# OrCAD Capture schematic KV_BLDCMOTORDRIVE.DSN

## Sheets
1 TITLE PAGE: title: FRDM-MC-LVBLDC; rev: X1; company: Freescale Semiconductor; note: SCH-XXXXX PDF: SPF-XXXXX; note: 6501 William Cannon Drive West; note: Austin, TX 78735-8598
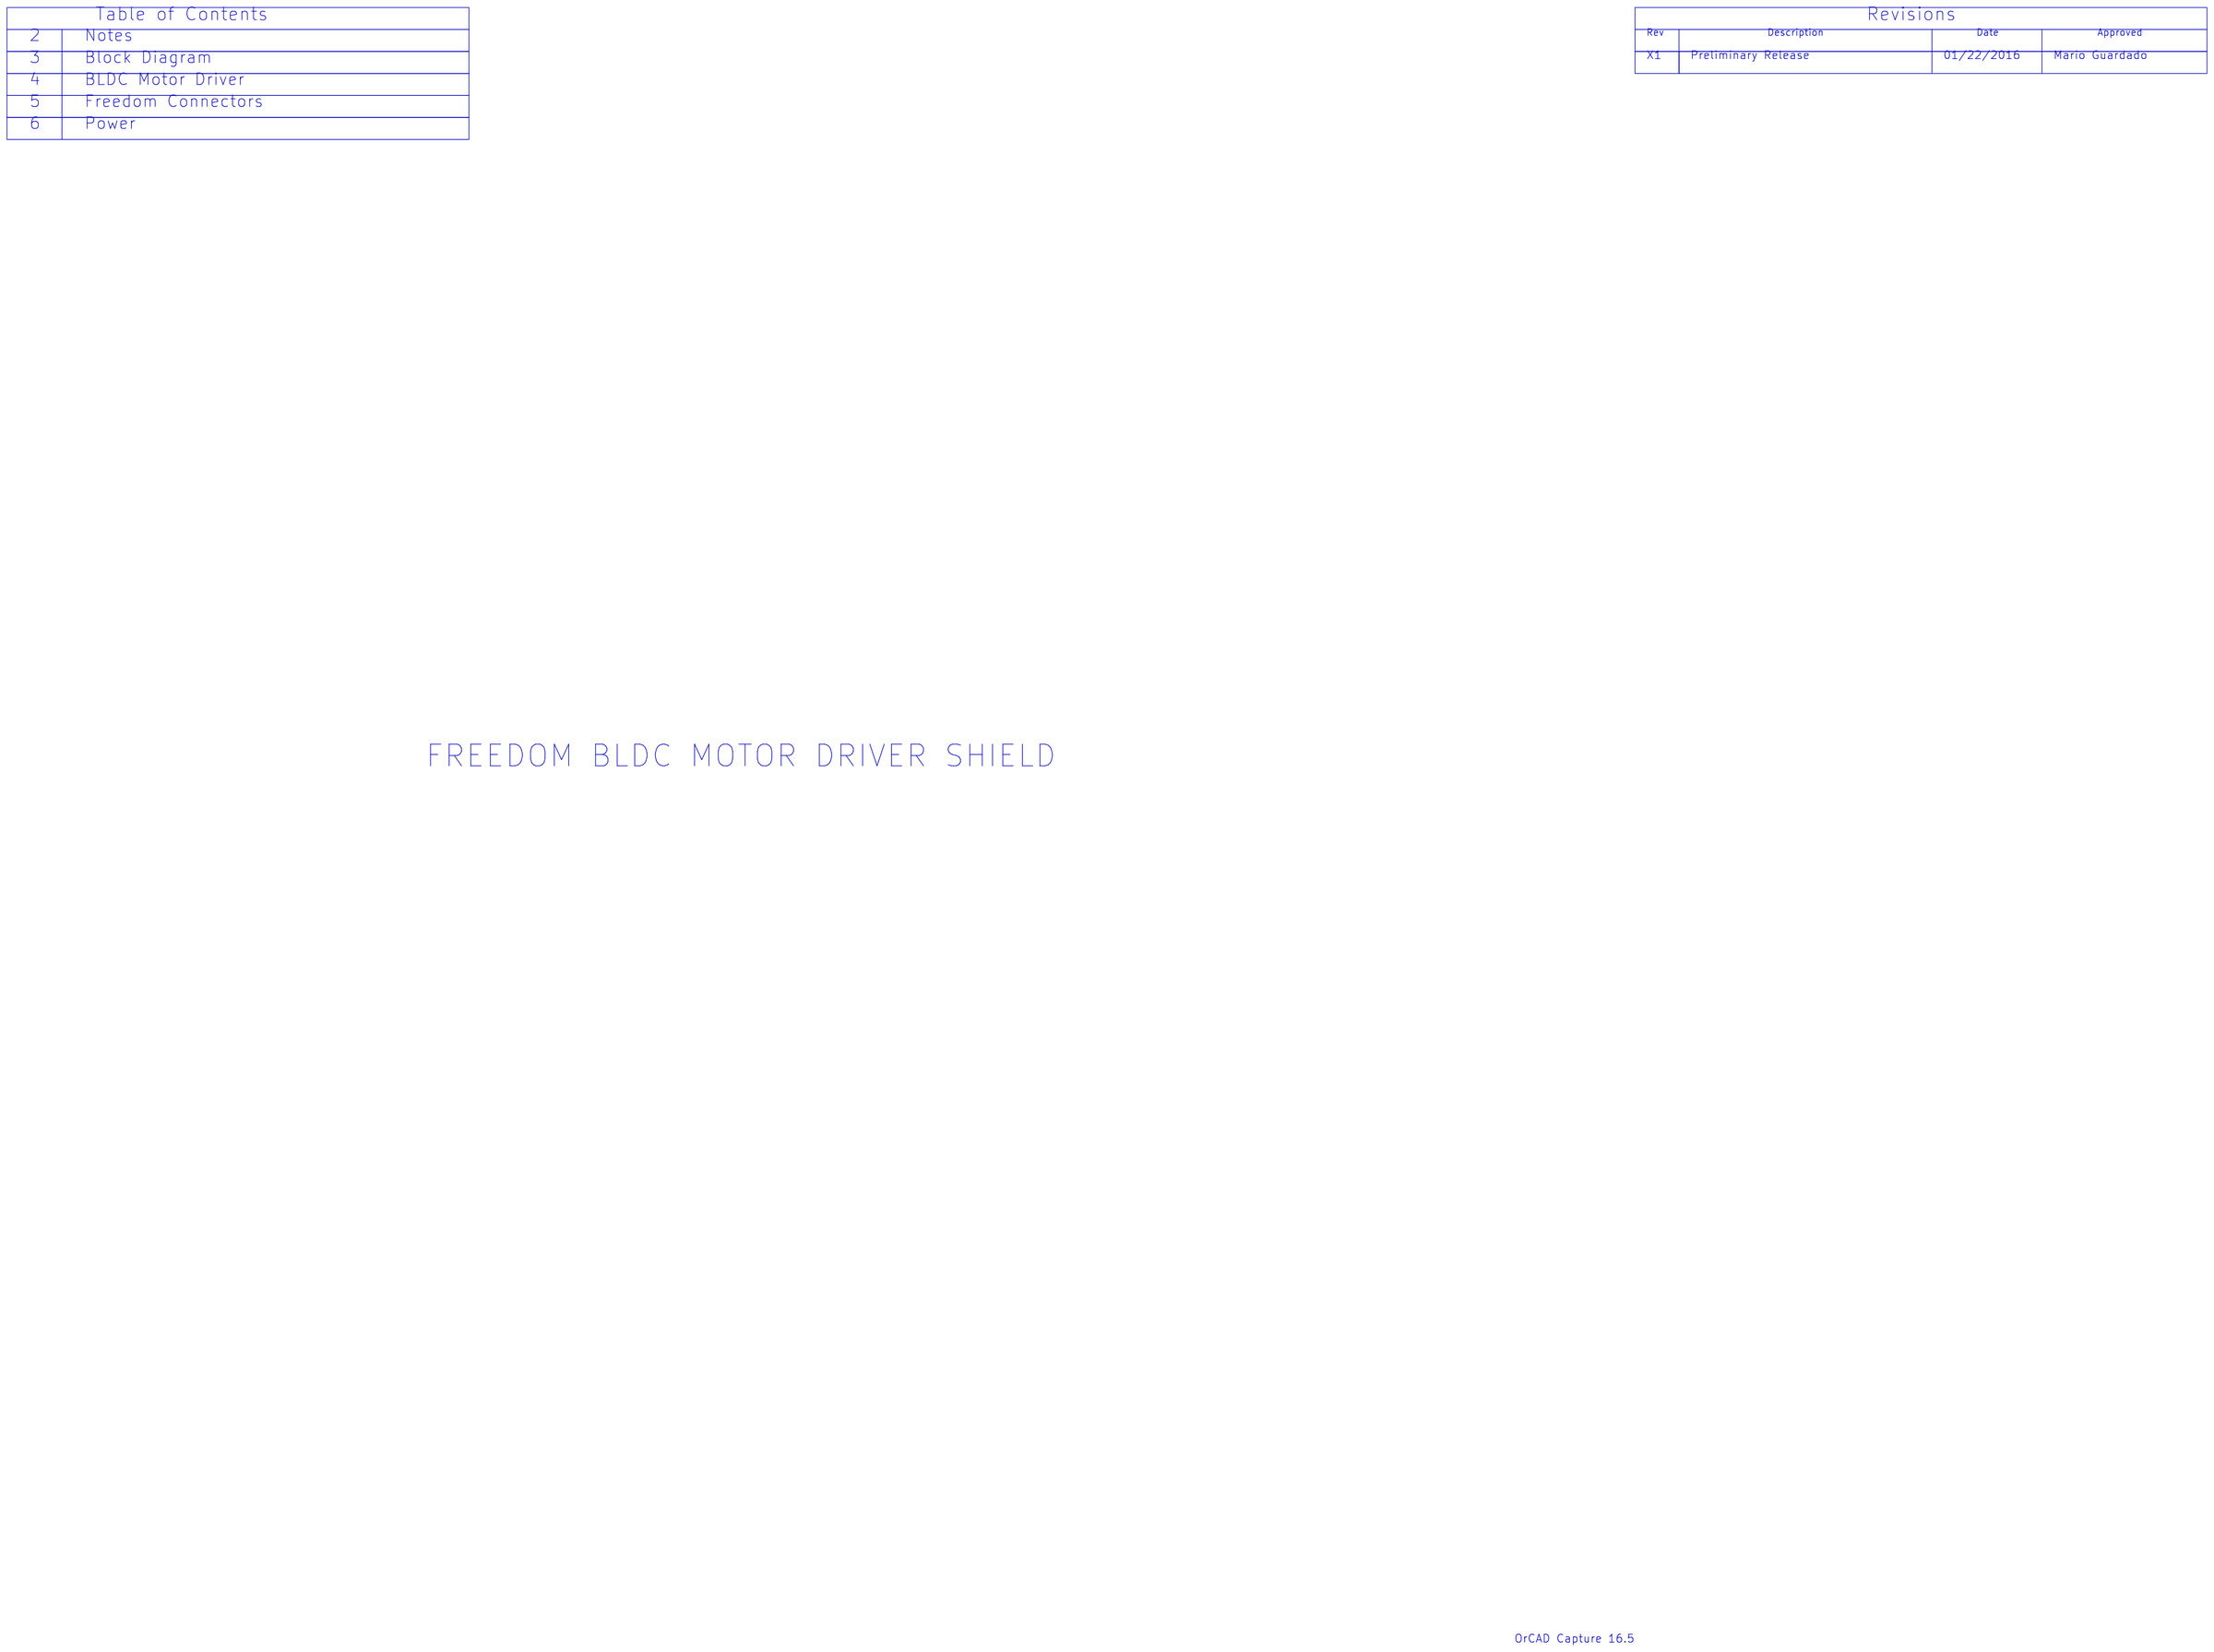
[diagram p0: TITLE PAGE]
2 NOTES
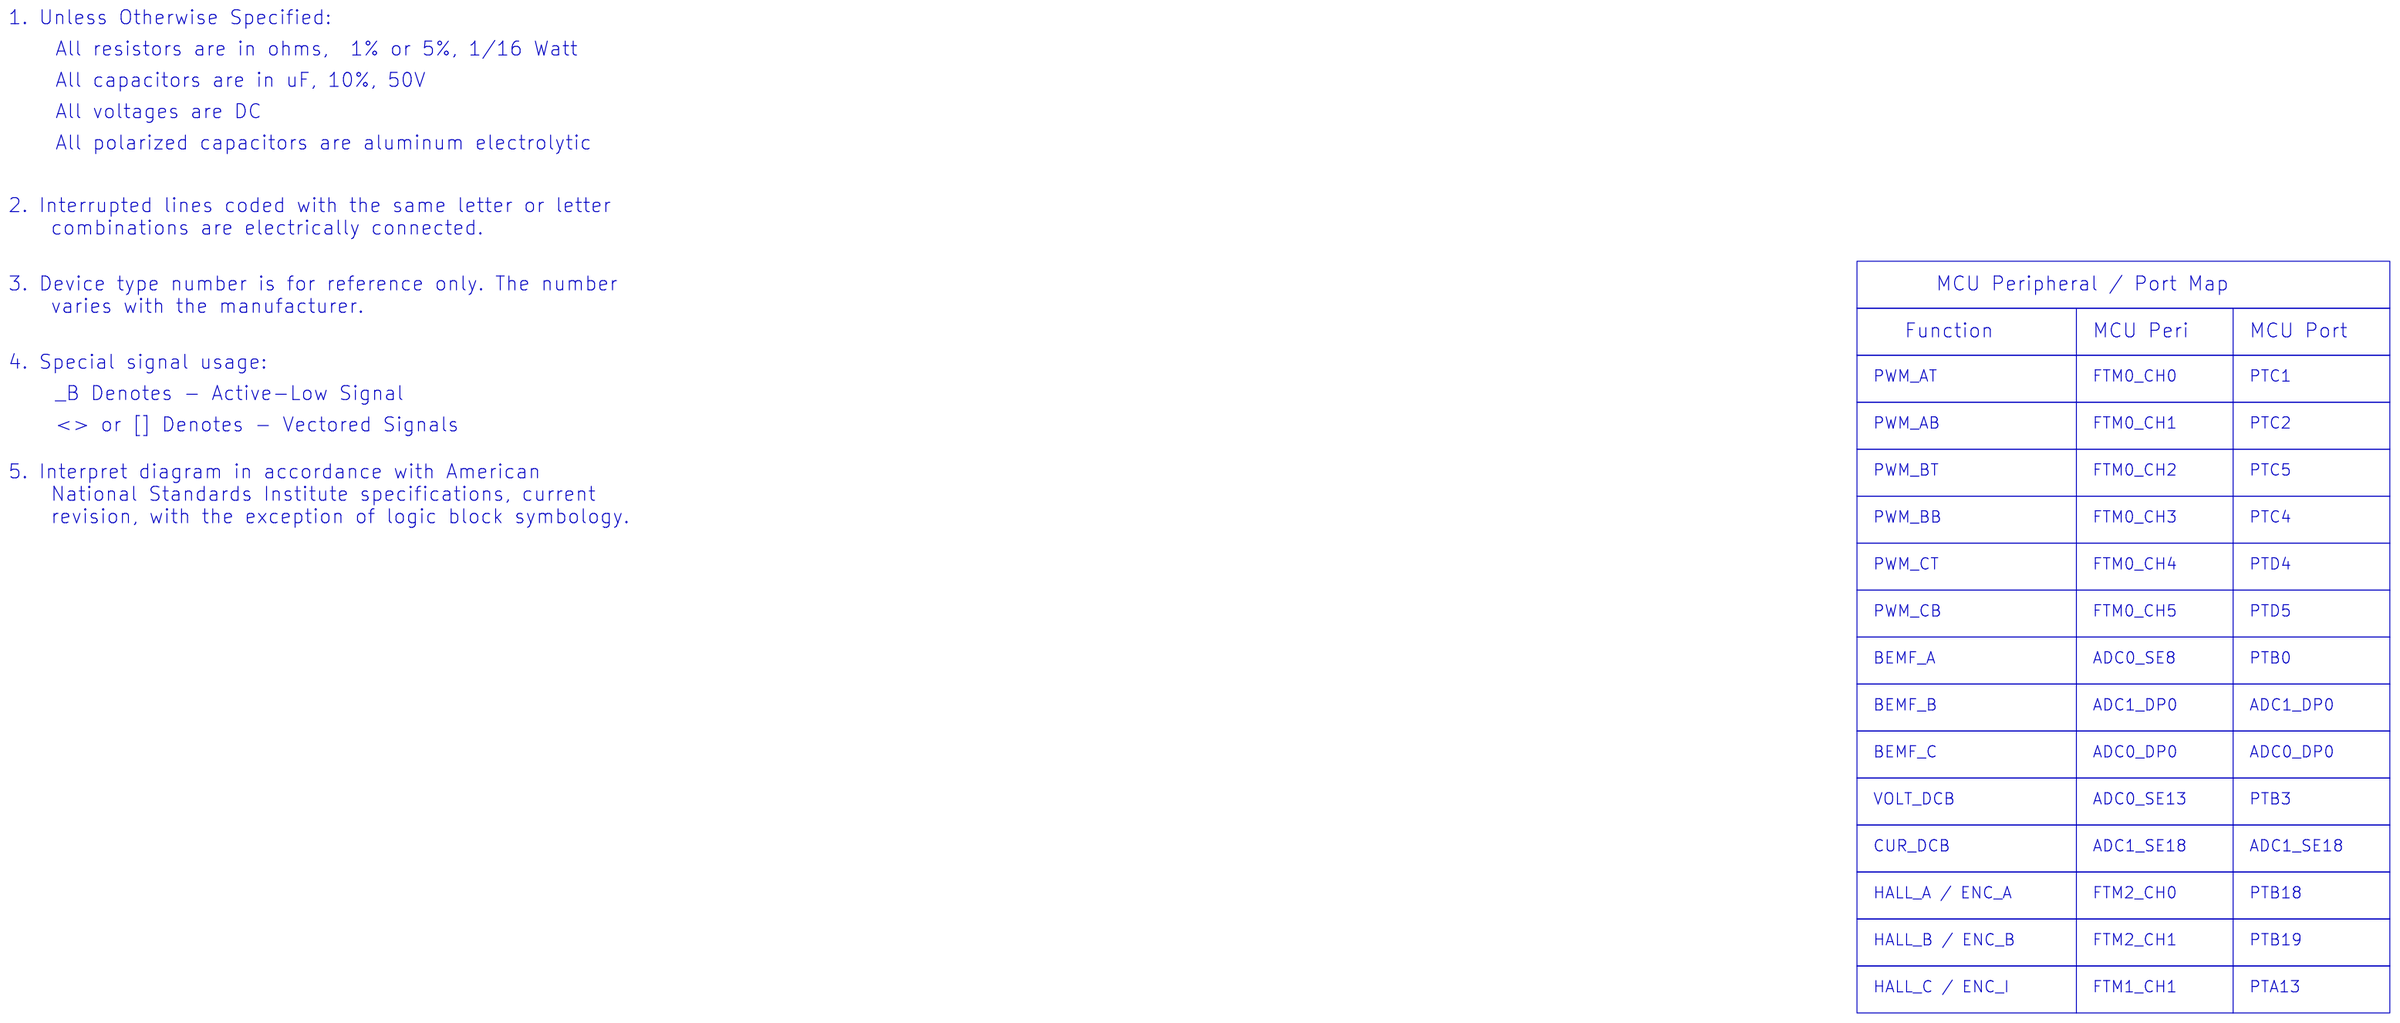
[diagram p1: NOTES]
3 BLOCK DIAGRAM
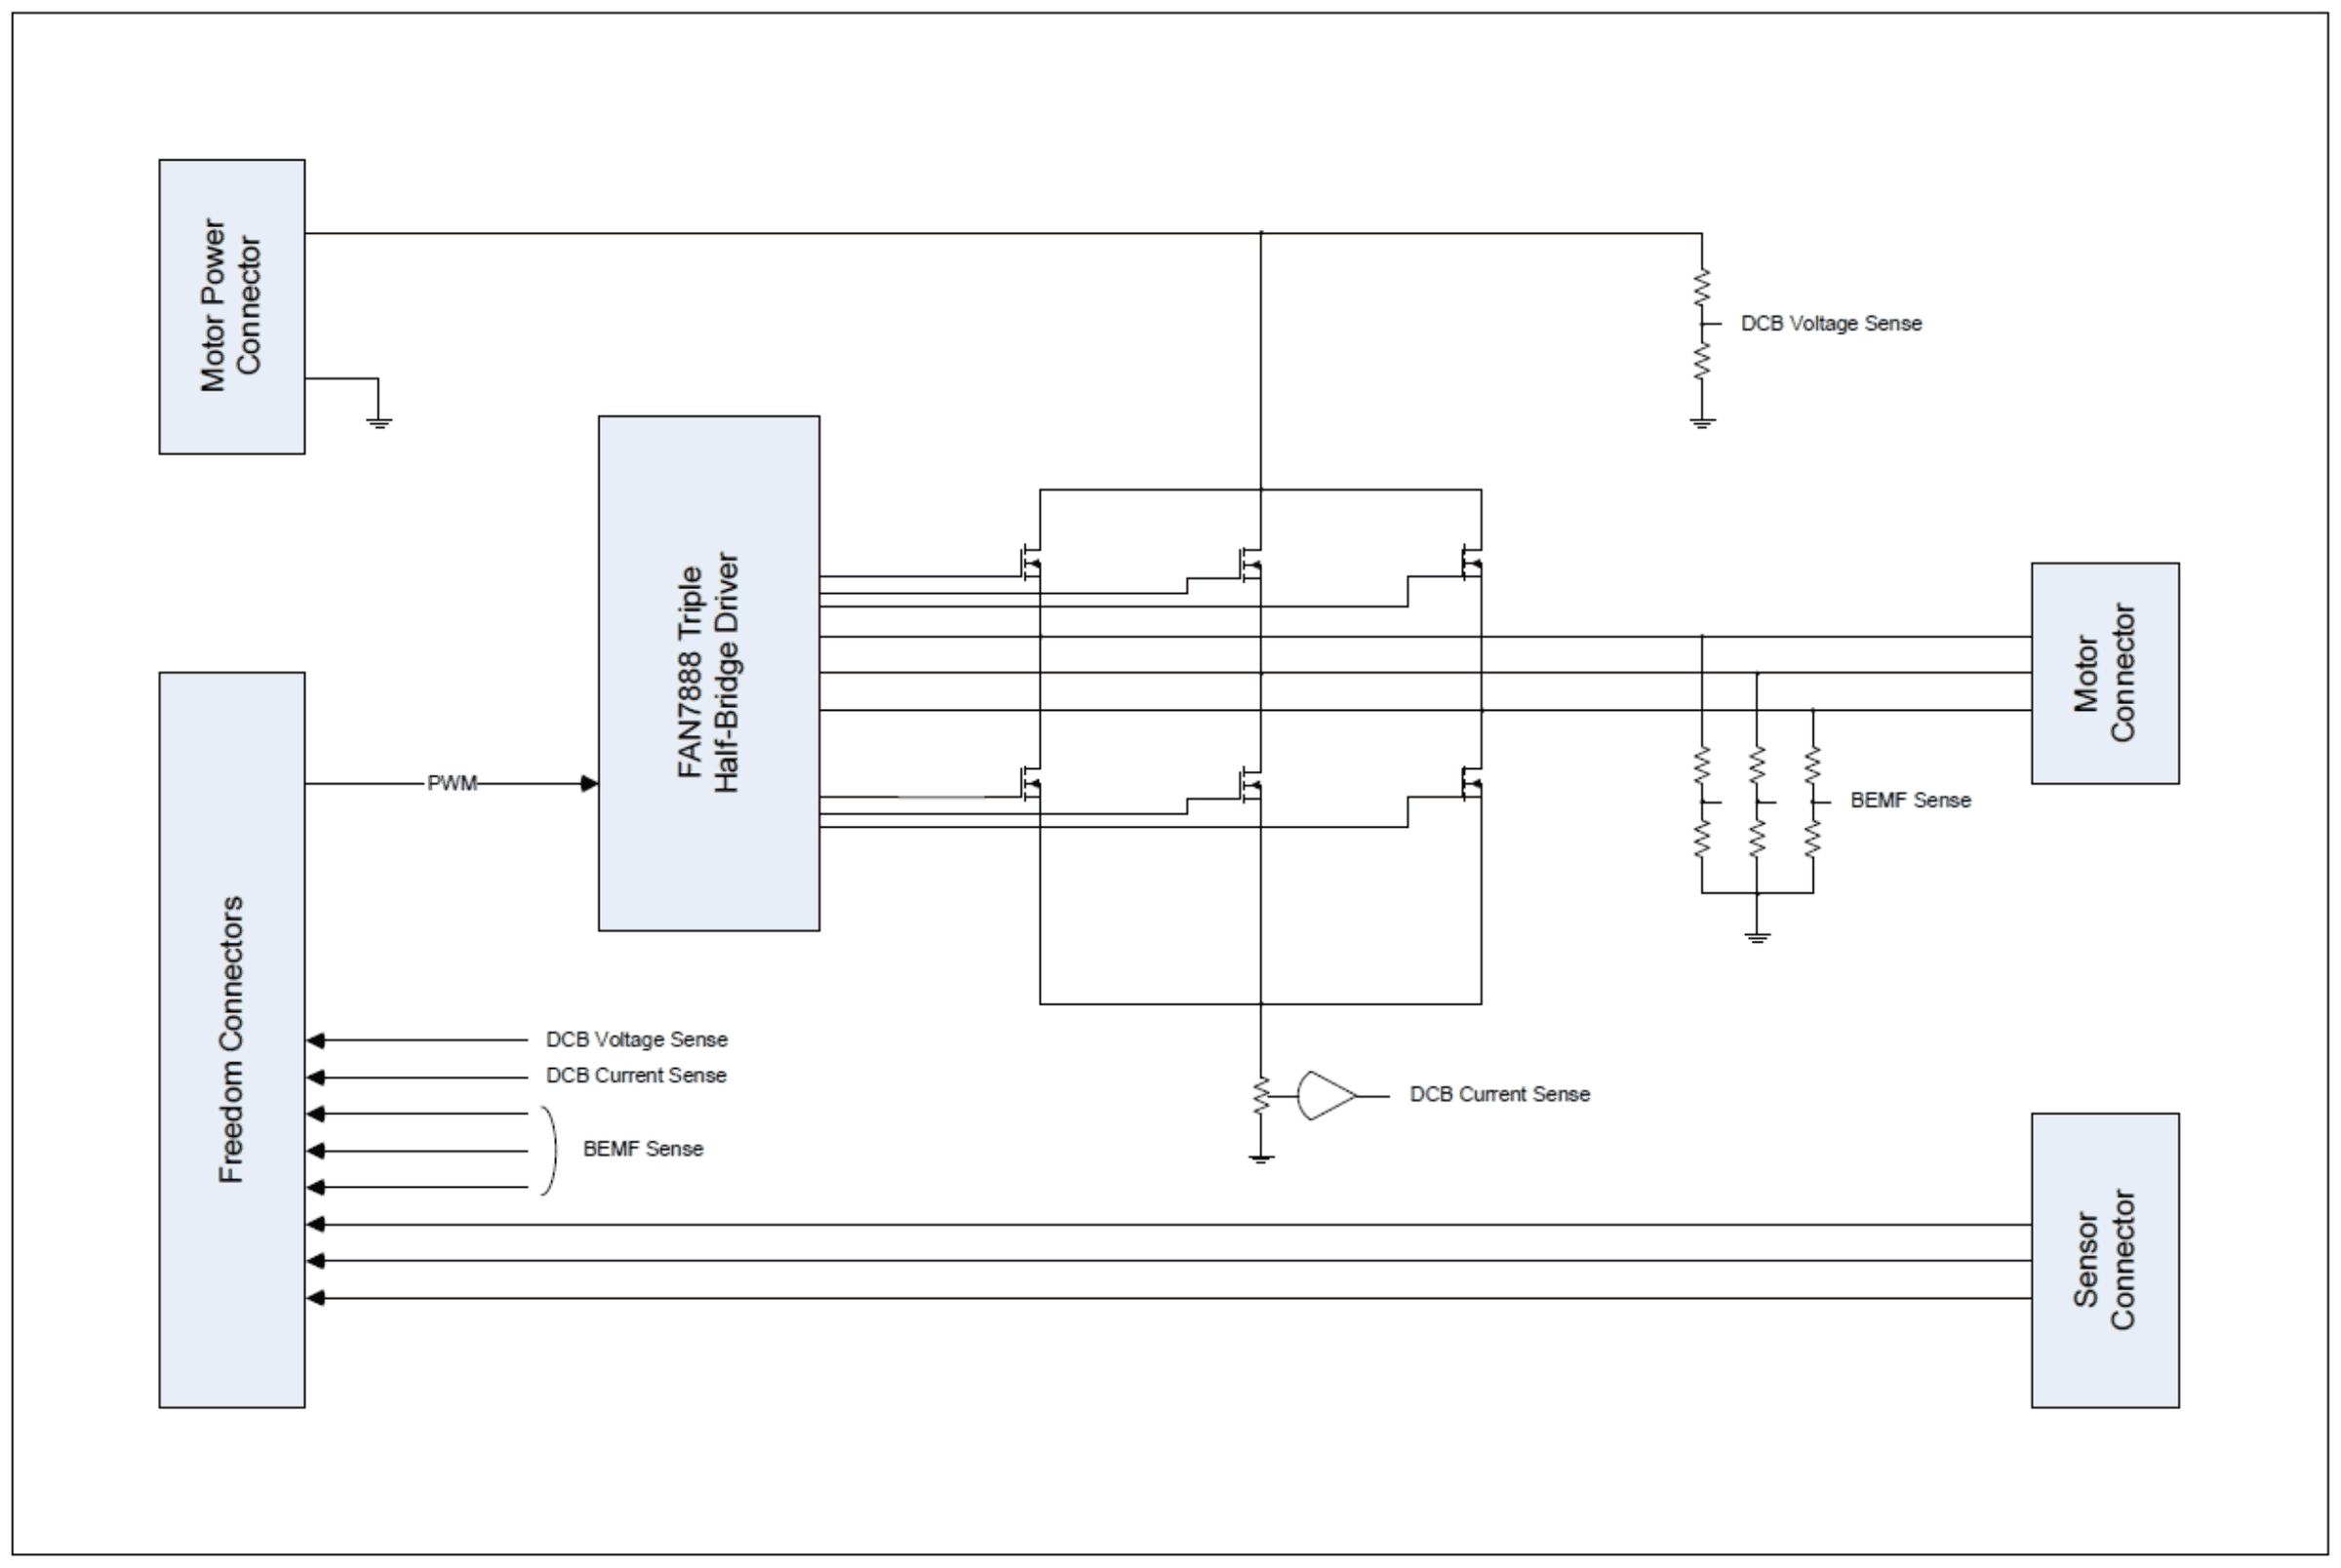
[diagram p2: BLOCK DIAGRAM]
4 MOTOR DRIVE: size C
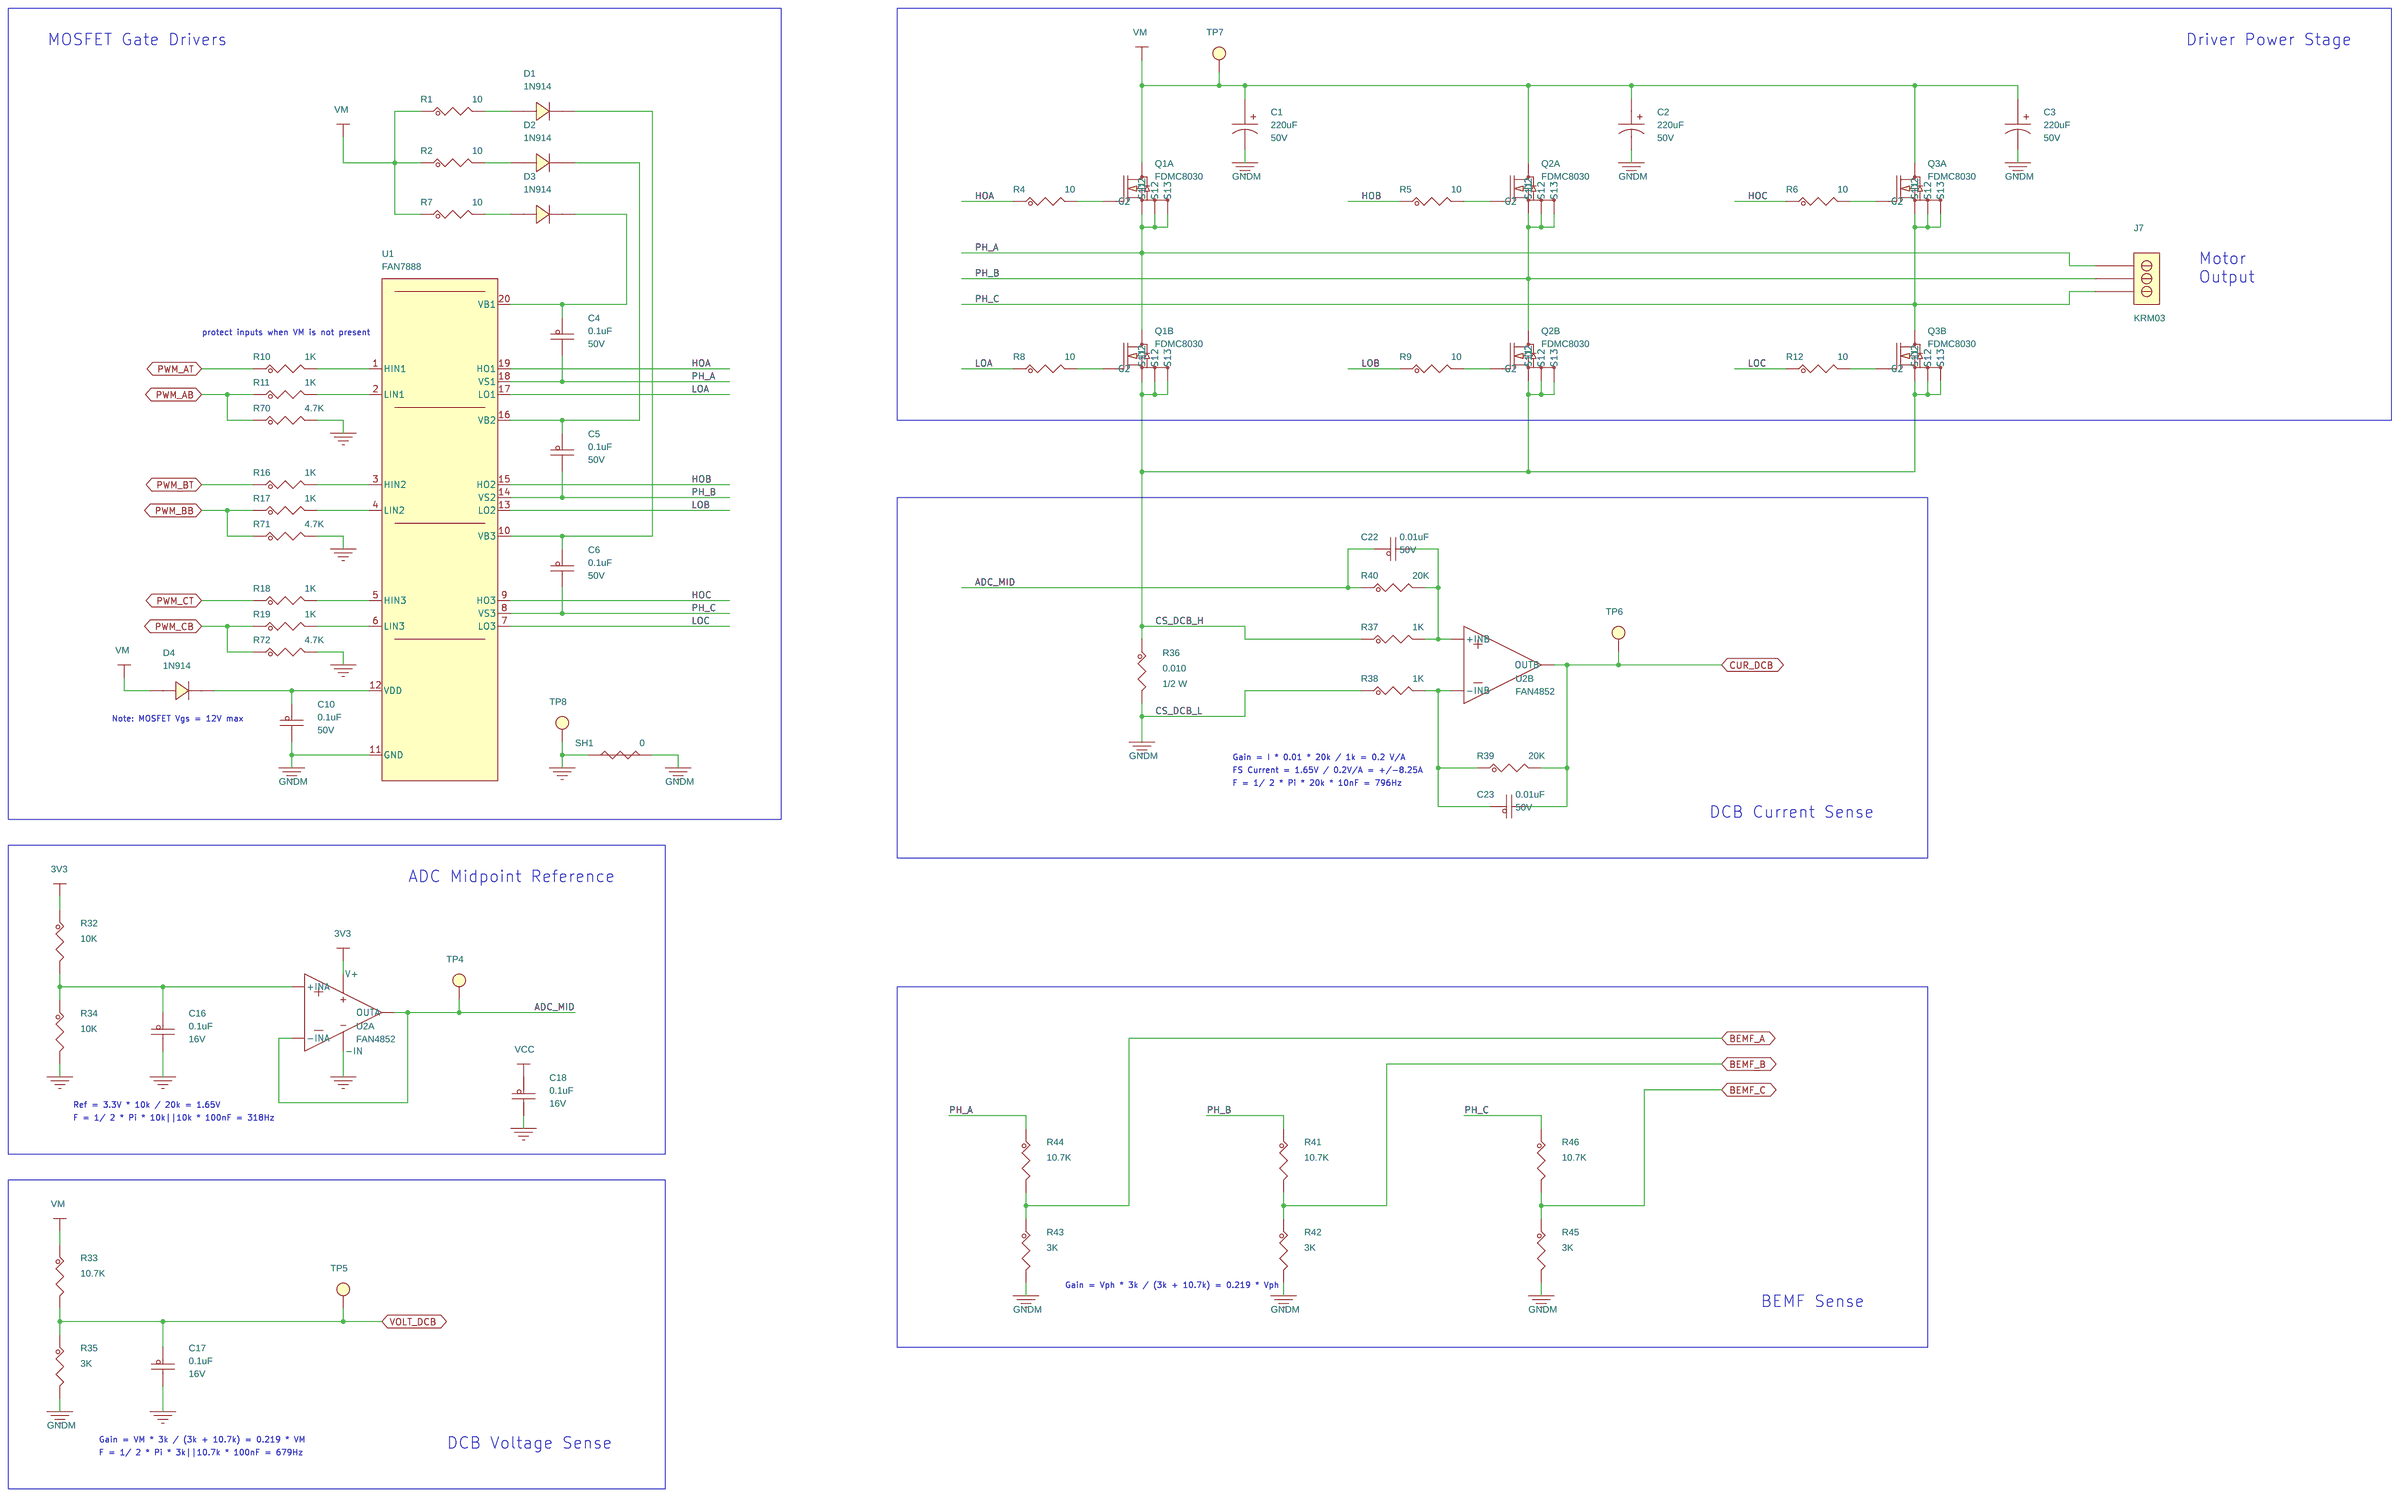
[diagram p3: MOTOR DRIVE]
5 MCU INTERFACE: size C
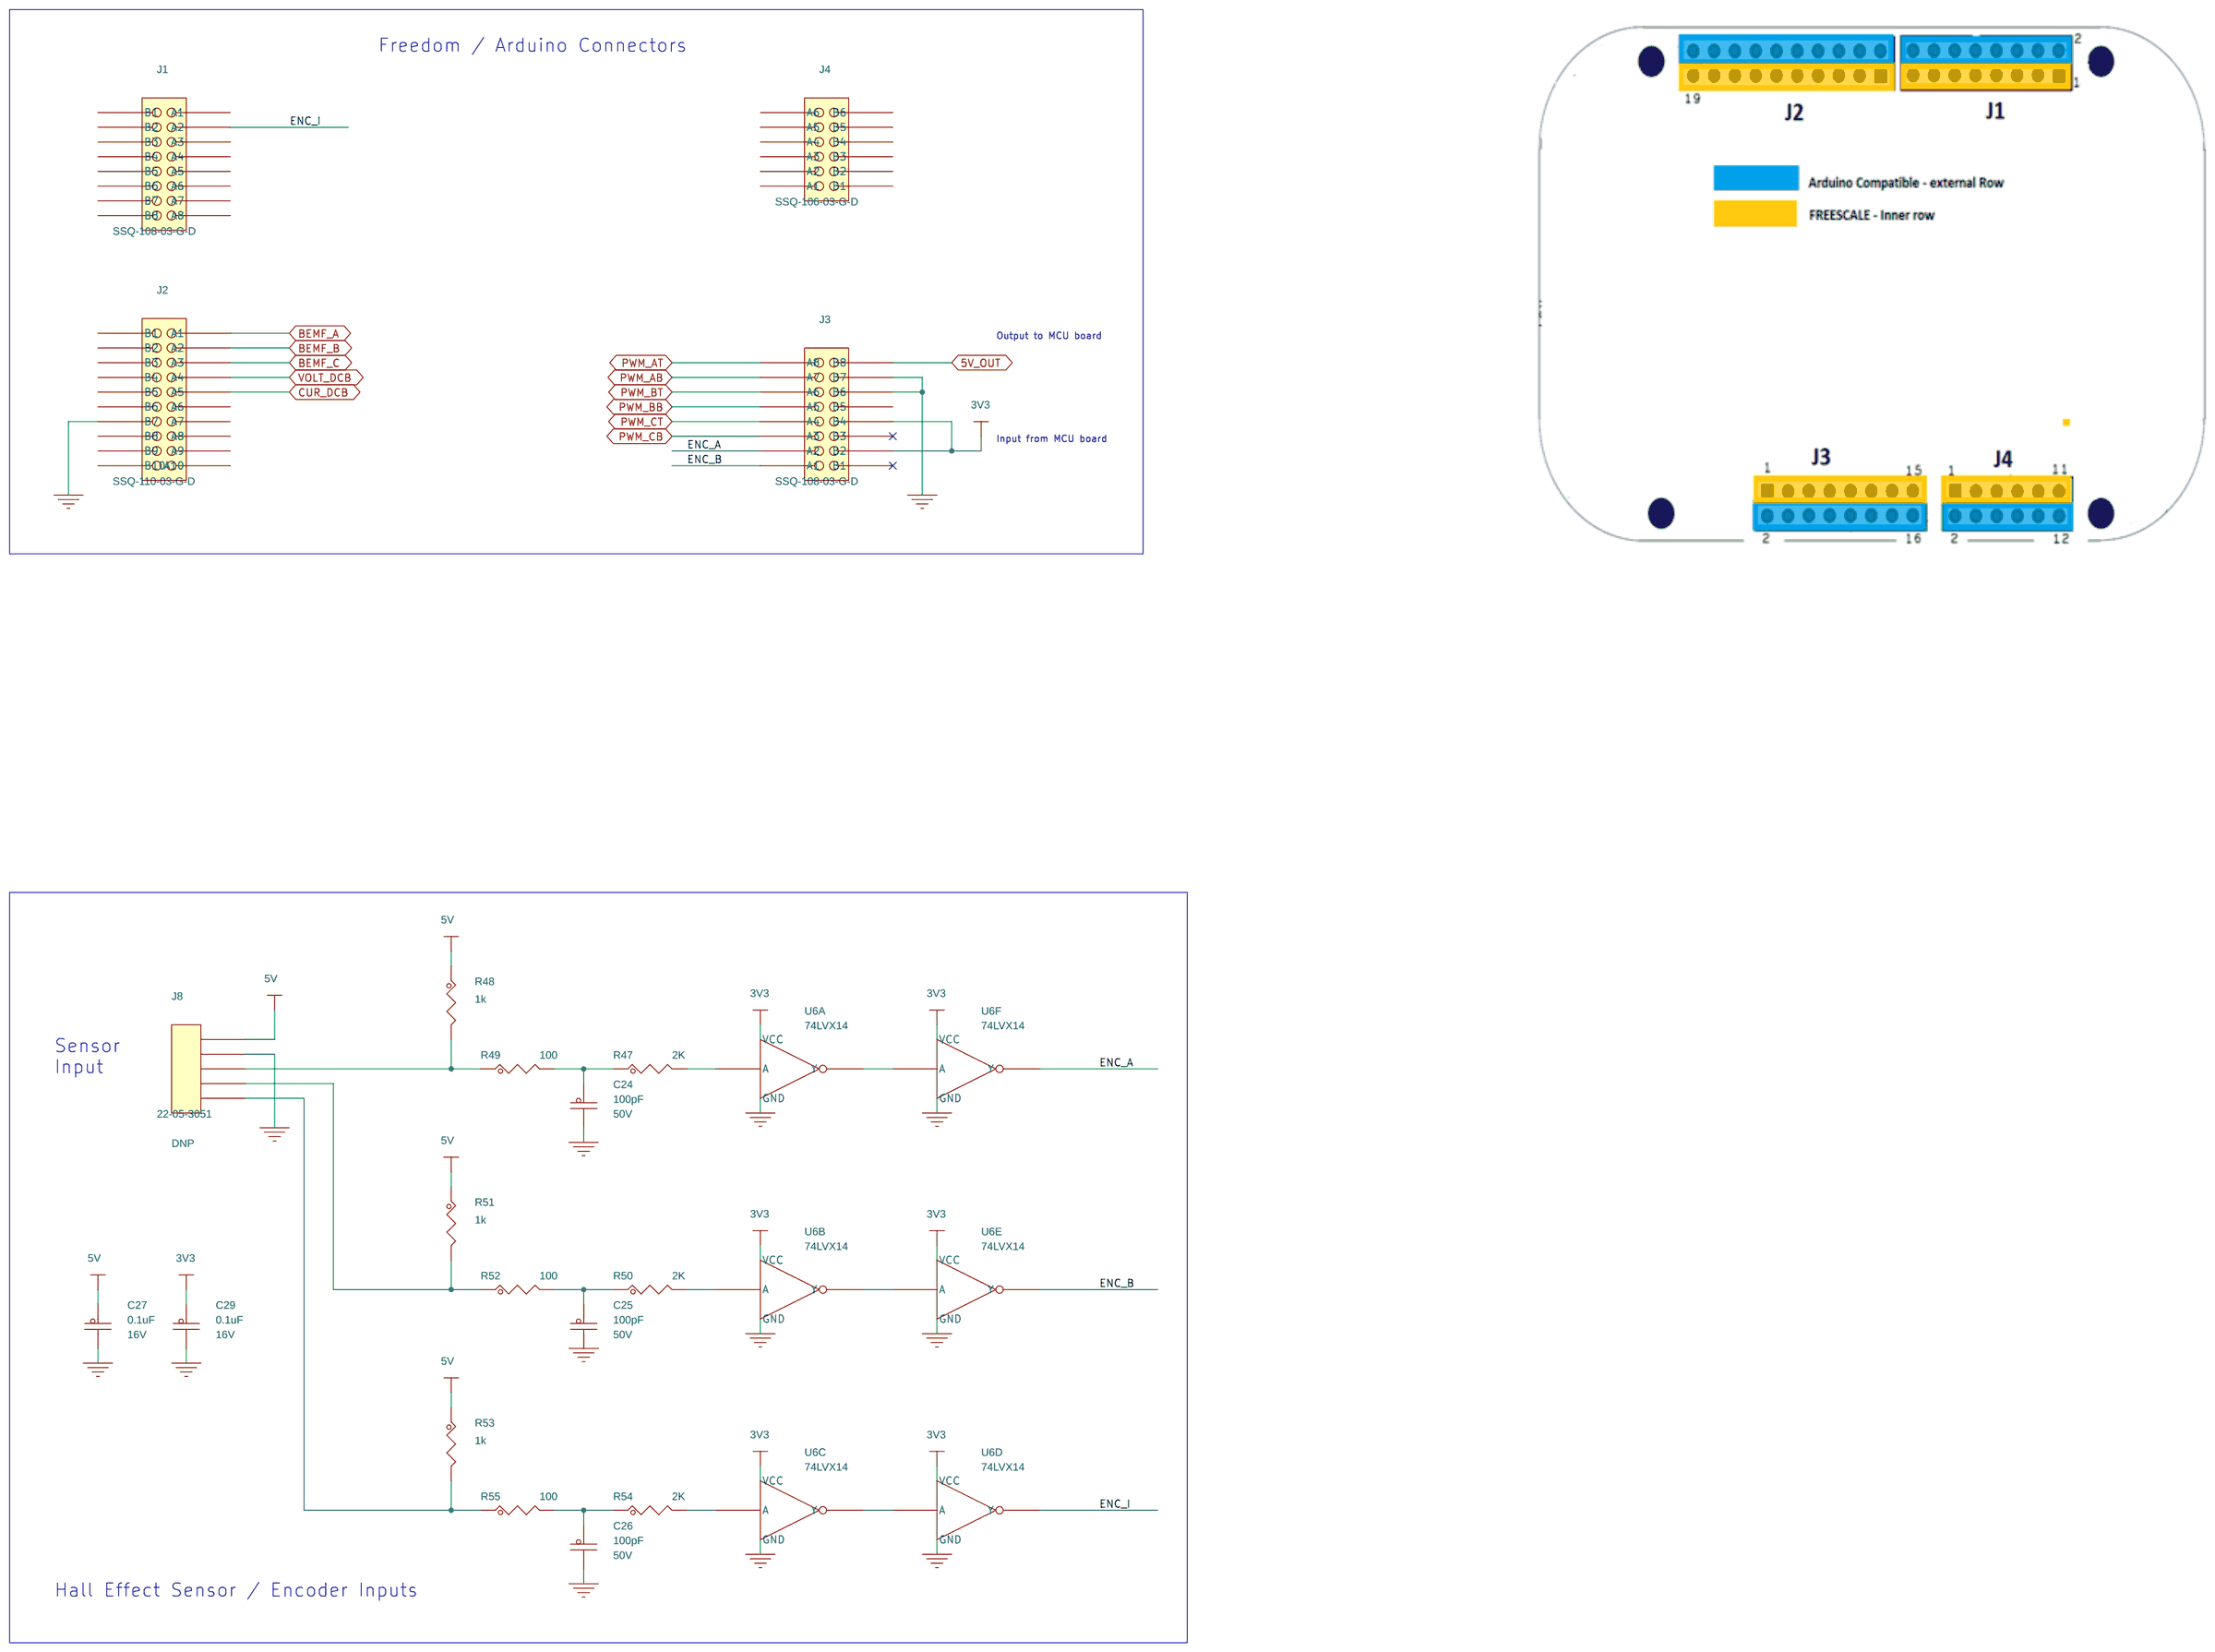
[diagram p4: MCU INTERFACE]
6 POWER: size C
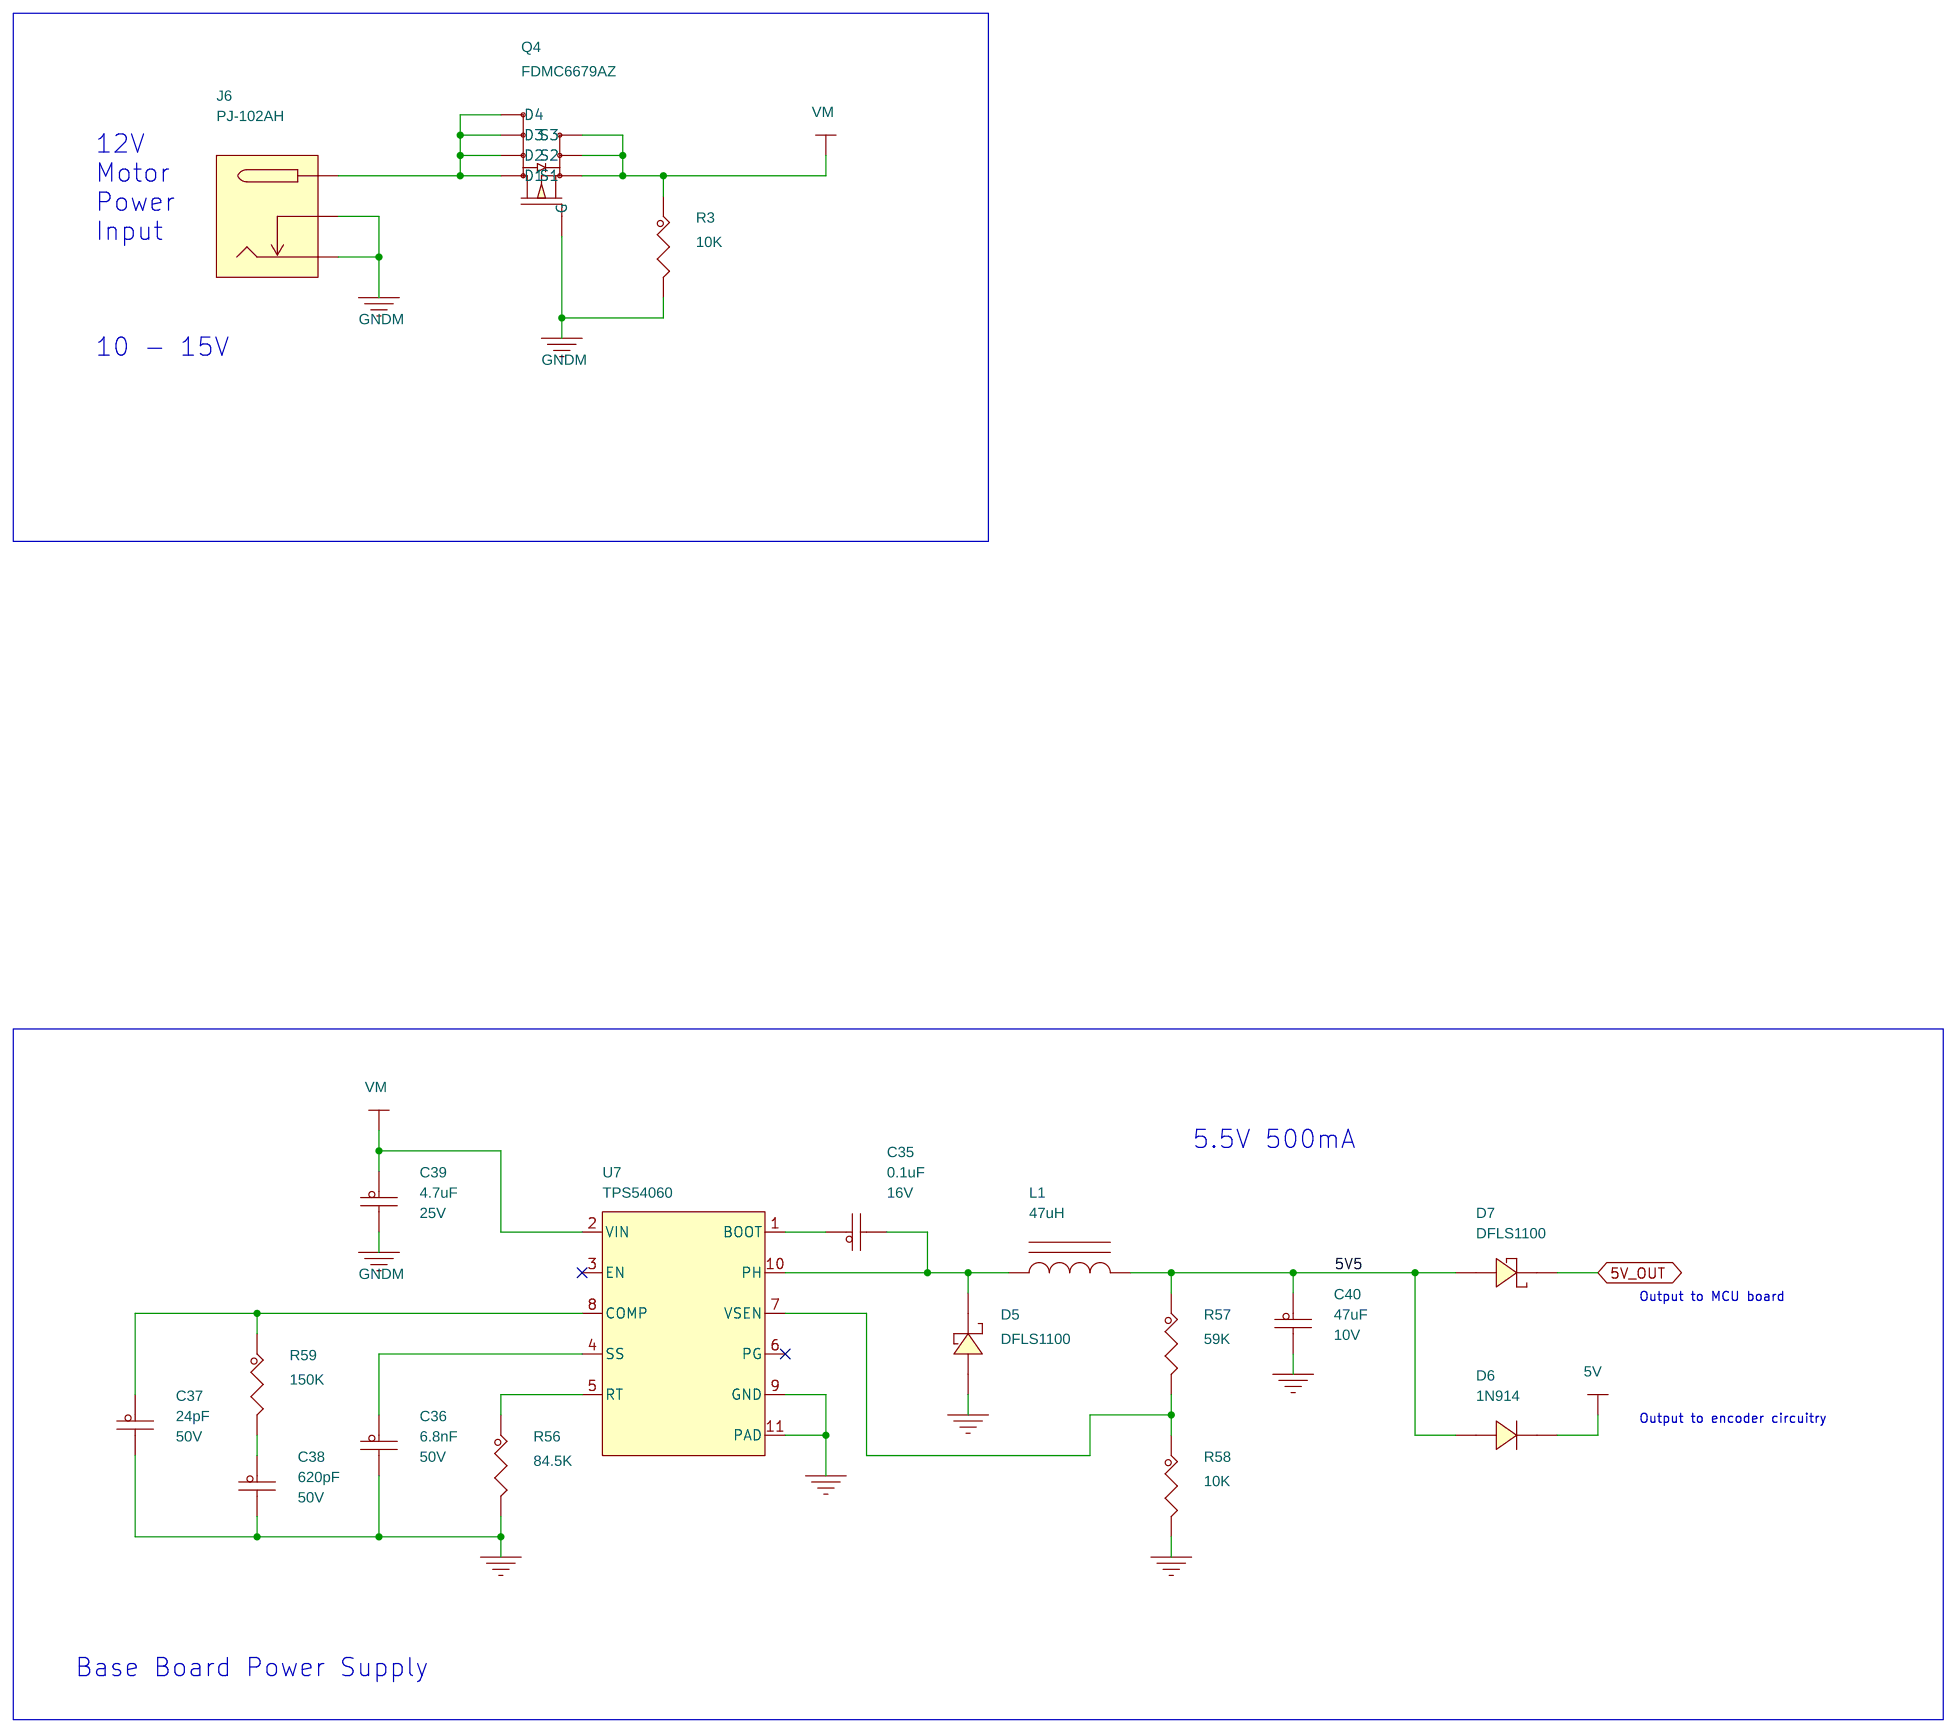
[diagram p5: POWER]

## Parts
sheet MCU INTERFACE
C24  100pF  [cc0402_25]
C25  100pF  [cc0402_25]
C26  100pF  [cc0402_25]
C27  0.1uF  [cc0402_25]
C29  0.1uF  [cc0402_25]
J1  SSQ-108-03-G-D  [SAMTEC_SSQ-108-03-G-D]
J2  SSQ-110-03-G-D  [SAMTEC_SSQ-110-03-G-D]
J3  SSQ-108-03-G-D  [SAMTEC_SSQ-108-03-G-D]
J4  SSQ-106-03-G-D  [SAMTEC_SSQ-106-03-G-D]
J8  22-05-3051  [CON_22-05-3051]
R47  2K  [rc0402_25]
R48  1k  [rc0402_25]
R49  100  [rc0402_25]
R50  2K  [rc0402_25]
R51  1k  [rc0402_25]
R52  100  [rc0402_25]
R53  1k  [rc0402_25]
R54  2K  [rc0402_25]
R55  100  [rc0402_25]
U6  74LVX14  [sop65p640x120-14n]  (sections A,B,C,D,E,F)
sheet MOTOR DRIVE
C1  220uF  [CAPRD_10x12p5mm]
C2  220uF  [CAPRD_10x12p5mm]
C3  220uF  [CAPRD_10x12p5mm]
C4  0.1uF  [cc0603_ov]
C5  0.1uF  [cc0603_ov]
C6  0.1uF  [cc0603_ov]
C10  0.1uF  [cc0603_ov]
C16  0.1uF  [cc0402_25]
C17  0.1uF  [cc0402_25]
C18  0.1uF  [cc0402_25]
C22  0.01uF  [cc0402_25]
C23  0.01uF  [cc0402_25]
D1  1N914  [SODFL2513x100N]
D2  1N914  [SODFL2513x100N]
D3  1N914  [SODFL2513x100N]
D4  1N914  [SODFL2513x100N]
J7  KRM03  [CON_KRM03]
Q1  FDMC8030  [POWER33-10]  (sections A,B)
Q2  FDMC8030  [POWER33-10]  (sections A,B)
Q3  FDMC8030  [POWER33-10]  (sections A,B)
R1  10  [rc0402_25]
R2  10  [rc0402_25]
R4  10  [rc0402_25]
R5  10  [rc0402_25]
R6  10  [rc0402_25]
R7  10  [rc0402_25]
R8  10  [rc0402_25]
R9  10  [rc0402_25]
R10  1K  [rc0402_25]
R11  1K  [rc0402_25]
R12  10  [rc0402_25]
R16  1K  [rc0402_25]
R17  1K  [rc0402_25]
R18  1K  [rc0402_25]
R19  1K  [rc0402_25]
R32  10K  [rc0402_25]
R33  10.7K  [rc0402_25]
R34  10K  [rc0402_25]
R35  3K  [rc0402_25]
R36  0.010  [rc1206_ov]
R37  1K  [rc0402_25]
R38  1K  [rc0402_25]
R39  20K  [rc0402_25]
R40  20K  [rc0402_25]
R41  10.7K  [rc0402_25]
R42  3K  [rc0402_25]
R43  3K  [rc0402_25]
R44  10.7K  [rc0402_25]
R45  3K  [rc0402_25]
R46  10.7K  [rc0402_25]
R70  4.7K  [rc0402_25]
R71  4.7K  [rc0402_25]
R72  4.7K  [rc0402_25]
SH1  0  [rc0402_25_ct]
TP4  TP  [TP_TH_040]
TP5  TP  [TP_TH_040]
TP6  TP  [TP_TH_040]
TP7  TP  [TP_TH_040]
TP8  TP  [TP_TH_040]
U1  FAN7888  [soic127p1032x265-20n]
U2  FAN4852  [sop65p490x110-8n]  (sections A,B)
sheet POWER
C35  0.1uF  [cc0402_25]
C36  6.8nF  [cc0402_25]
C37  24pF  [cc0402_25]
C38  620pF  [cc0402_25]
C39  4.7uF  [cc1206_ov]
C40  47uF  [cc1206_ov]
D5  DFLS1100  [SODFL3718X100N]
D6  1N914  [SODFL2513x100N]
D7  DFLS1100  [SODFL3718X100N]
J6  PJ-102AH  [CON_PJ-102AH]
L1  47uH  [IND_SRN8040]
Q4  FDMC6679AZ  [POWER33-8]
R3  10K  [rc0402_25]
R56  84.5K  [rc0402_25]
R57  59K  [rc0402_25]
R58  10K  [rc0402_25]
R59  150K  [rc0402_25]
U7  TPS54060  [SOP50P490X110-11N]

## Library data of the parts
C24-C26 = CAP_NP: CAP, CER 100PF 50V 5% C0G 0402; MFG_NAME01: KEMET; MFG_PN01: C0402C101J5GACTU; VOLTAGE: 50V
C16-C18 C27 C29 C35 = CAP_NP: CAP, CER 0.1UF 16V 10% X7R 0402; MFG_NAME01: KEMET; MFG_PN01: C0402C104K4RACTU; VOLTAGE: 16V
J1 J3 = CONN_2x8
J2 = CONN_2x10
J4 = CONN_2x6
J8 = CON5: CONNECTOR, 5-pin, 100mil; ASSY_OPT: DNP; MFG_NAME01: MOLEX
R47 R50 R54 = RES: RES, MF 2K 1/16W 1% 0402; MFG_PN01: CRCW04022K00FKED
R10 R11 R16-R19 R37 R38 R48 R51 R53 = RES: RES, MF 1K 1/16W 1% 0402; MFG_PN01: CRCW04021K00FKED
R49 R52 R55 = RES: RES, MF 100 1/16W 1% 0402; MFG_PN01: CRCW0402100RFKED
U6 = 74LVX14
C1-C3 = CAP_POL: CAP, POL, 220UF 50V 20%; CLASS: DISCRETE; MFG_NAME01: NICHICON; MFG_PN01: UVK1H221MPD; VOLTAGE: 50V
C4-C6 C10 = CAP_NP: CAP, CER 0.1UF 50V 10% X7R 0603; MFG_NAME01: KEMET; MFG_PN01: C0603C104K5RACTU; VOLTAGE: 50V
C22 C23 = CAP_NP: CAP, CER 0.01UF 50V 10% X7R 0402; MFG_NAME01: KEMET; MFG_PN01: C0402C103K5RACTU; VOLTAGE: 50V
D1-D4 D6 = 1N914BWS
J7 = KRM03
Q1-Q3 = FDMC8030: MOSFET, DUAL N-CH, 40V
R1 R2 R4-R9 R12 = RES: MFG_PN01: CRCW040210R0JNED
R3 R32 R34 R58 = RES: RES, MF 10K 1/16W 1% 0402; MFG_PN01: CRCW040210K0FKED
R33 R41 R44 R46 = RES: RES, MF 10.7K 1/16W 1% 0402; MFG_PN01: CRCW040210K7FKED
R35 R42 R43 R45 = RES: RES, MF 3K 1/16W 1% 0402; MFG_PN01: CRCW04023K00FKED
R36 = RES: RES, MF 0.01 1/2W 1% 1206; MFG_NAME01: SEI; MFG_PN01: CSR1206FT10L0; Power: 1/2 W
R39 R40 = RES: RES, MF 20K 1/16W 1% 0402; MFG_PN01: CRCW040220K0FKED
R70-R72 = RES: RES, MF 4.7K 1/16W 5% 0402; MFG_PN01: CRCW04024K70JNED
SH1 = SH_RES: CUT TRACE RESISTOR; MFG_NAME01: NOTACOMPONENT; MFG_PN01: NOTACOMPONENT
TP4-TP8 = TP
U1 = FAN7888
U2 = FAN4852: IC, OP AMP, DUAL
C36 = CAP_NP: CAP, CER 6.8NF 50V 10% X7R 0402; MFG_NAME01: KEMET; MFG_PN01: C0402C682K5RACTU; VOLTAGE: 50V
C37 = CAP_NP: CAP, CER 24PF 50V 5% C0G 0402; MFG_NAME01: KEMET; MFG_PN01: C0402C240J5GACTU; VOLTAGE: 50V
C38 = CAP_NP: CAP, CER 620PF 50V 5% C0G 0402; MFG_NAME01: KEMET; MFG_PN01: C0402C621J5GACTU; VOLTAGE: 50V
C39 = CAP_NP: CAP, CER 4.7UF 25V 10% X7R 1206; MFG_NAME01: TDK; MFG_PN01: C3216X7R1E475K085AB; VOLTAGE: 25V
C40 = CAP_NP: CAP, CER 47UF 10V 20% X5R 1206; MFG_NAME01: MURATA; MFG_PN01: GRM31CR61A476ME15L; VOLTAGE: 10V
D5 D7 = DFLS1100
J6 = PJ-102AH: CONNECTOR, BARREL
L1 = SRN8040: INDUCTOR, 47UH; MFG_PN01: SRN8040-470M
Q4 = FDMC6679AZ: MOSFET, P-CH, 30V; AGILE_PN: agilepn
R56 = RES: RES, MF 84.5K 1/16W 1% 0402; MFG_PN01: CRCW040284K5FKED
R57 = RES: RES, MF 59K 1/16W 1% 0402; MFG_PN01: CRCW040259K0FKED
R59 = RES: RES, MF 150K 1/16W 1% 0402; MFG_PN01: CRCW0402150KFKED
U7 = TPS54060

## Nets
3V3: C18.1 C29.1 J3.4(B2) J3.8(B4) R32.1 U2.8(V+) U6.14(VCC)
5V: C27.1 D6.C J8.1 R48.1 R51.1 R53.1
5V5: C40.1 D6.A D7.A L1.2 R57.1
5V_OUT: D7.C J3.16(B8)
GND: C16.2 C17.2 C18.2 C24.2 C25.2 C26.2 C27.2 C29.2 C36.2 C37.2 C38.2 C40.2 D5.A J2.14(B7) J3.12(B6) J3.14(B7) J8.2 R34.2 R56.2 R58.2 R70.2 R71.2 R72.2 SH1.1 TP8.1(TP) U2.4(-IN) U6.7(GND) U7.9(GND) U7.11(PAD)
GNDM: C1.2(MINUS) C2.2(MINUS) C3.2(MINUS) C10.2 C39.2 J6.2 J6.3 Q4.4(G) R3.2 R35.2 R36.2 R38.1 R42.2 R43.2 R45.2 SH1.2 U1.11(GND)
ADC_MID: C22.1 R40.1 TP4.1(TP) U2.1(OUTA) U2.2(-INA)
BEMF_A: J2.1(A1) R43.1 R44.2
BEMF_B: J2.3(A2) R41.2 R42.1
BEMF_C: J2.5(A3) R45.1 R46.2
CS_DCB_H: Q1.5(S13) Q1.6(S12) Q1.7(S11) Q2.5(S13) Q2.6(S12) Q2.7(S11) Q3.5(S13) Q3.6(S12) Q3.7(S11) R36.1 R37.1
CUR_DCB: C23.2 J2.9(A5) R39.2 TP6.1(TP) U2.7(OUTB)
ENC_A: J3.3(A2) U6.12(Y)
ENC_B: J3.1(A1) U6.10(Y)
ENC_I: J1.3(A2) U6.8(Y)
HOA: R4.1 U1.19(HO1)
HOB: R5.1 U1.15(HO2)
HOC: R6.1 U1.9(HO3)
LOA: R8.1 U1.17(LO1)
LOB: R9.1 U1.13(LO2)
LOC: R12.1 U1.7(LO3)
PH_A: C4.2 J7.1 Q1.2(S11) Q1.3(S12) Q1.4(S13) Q1.10(D2) R44.1 U1.18(VS1)
PH_B: C5.2 J7.2 Q2.2(S11) Q2.3(S12) Q2.4(S13) Q2.10(D2) R41.1 U1.14(VS2)
PH_C: C6.2 J7.3 Q3.2(S11) Q3.3(S12) Q3.4(S13) Q3.10(D2) R46.1 U1.8(VS3)
PWM_AB: J3.13(A7) R11.1 R70.1
PWM_AT: J3.15(A8) R10.1
PWM_BB: J3.9(A5) R17.1 R71.1
PWM_BT: J3.11(A6) R16.1
PWM_CB: J3.5(A3) R19.1 R72.1
PWM_CT: J3.7(A4) R18.1
VM: C1.1(PLUS) C2.1(PLUS) C3.1(PLUS) C39.1 D4.A Q1.9(D2) Q2.9(D2) Q3.9(D2) Q4.1(S1) Q4.2(S2) Q4.3(S3) R1.1 R2.1 R3.1 R7.1 R33.1 TP7.1(TP) U7.2(VIN)
VOLT_DCB: C17.1 J2.7(A4) R33.2 R35.1 TP5.1(TP)
N24033468: C4.1 D3.C U1.20(VB1)
N24033594: C5.1 D2.C U1.16(VB2)
N24033653: C6.1 D1.C U1.10(VB3)
N24035180: D1.A R1.2
N24035201: D2.A R2.2
N24035206: D3.A R7.2
N24035227: Q1.1(G2) R4.2
N24035245: Q1.8(G2) R8.2
N24035263: Q2.1(G2) R5.2
N24035281: Q2.8(G2) R9.2
N24035326: Q3.8(G2) R12.2
N24035327: Q3.1(G2) R6.2
N24037051: C10.1 D4.C U1.12(VDD)
N24055425: C16.1 R32.2 R34.1 U2.3(+INA)
N24056935: R18.2 U1.5(HIN3)
N24056936: R16.2 U1.3(HIN2)
N24056937: R10.2 U1.1(HIN1)
N24056938: R19.2 U1.6(LIN3)
N24056939: R17.2 U1.4(LIN2)
N24056940: R11.2 U1.2(LIN1)
N24071789: C22.2 R37.2 R40.2 U2.5(+INB)
N24071791: C23.1 R38.2 R39.1 U2.6(-INB)
N24077170: C24.1 R47.1 R49.2
N24077180: J8.3 R48.2 R49.1
N24077887: J8.4 R51.2 R52.1
N24077889: C25.1 R50.1 R52.2
N24077981: J8.5 R53.2 R55.1
N24077985: C26.1 R54.1 R55.2
N24130653: R47.2 U6.1(A)
N24130655: R50.2 U6.3(A)
N24130657: R54.2 U6.5(A)
N24130659: U6.6(Y) U6.9(A)
N24130661: U6.4(Y) U6.11(A)
N24130663: U6.2(Y) U6.13(A)
N24141092: J6.1 Q4.5(D1) Q4.6(D2) Q4.7(D3) Q4.8(D4)
N24147614: C35.1 U7.1(BOOT)
N24147651: C35.2 D5.C L1.1 U7.10(PH)
N24147683: R57.2 R58.1 U7.7(VSEN)
N24147707: R56.1 U7.5(RT)
N24147711: C36.1 U7.4(SS)
N24147721: C37.1 R59.1 U7.8(COMP)
N24147753: C38.1 R59.2

Not connected (* = marked no-connect by the designer): J1 1(A1) 2(B1) 4(B2) 5(A3) 6(B3) 7(A4) 8(B4) 9(A5) 10(B5) 11(A6) 12(B6) 13(A7) 14(B7) 15(A8) 16(B8); J2 2(B1) 4(B2) 6(B3) 8(B4) 10(B5) 11(A6) 12(B6) 13(A7) 15(A8) 16(B8) 17(A9) 18(B9) 19(A10) 20(B10); J3 2(B1)* 6(B3)* 10(B5); J4 1(A1) 2(B1) 3(A2) 4(B2) 5(A3) 6(B3) 7(A4) 8(B4) 9(A5) 10(B5) 11(A6) 12(B6); U7 3(EN)* 6(PG)*

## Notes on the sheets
sheet 1
- Table of Contents
- Revisions
- 2
- Notes
- Rev
- Description
- Date
- Approved
- 3
- Block Diagram
- X1
- Preliminary Release
- 01/22/2016
- Mario Guardado
- 4
- BLDC Motor Driver
- 5
- Freedom Connectors
- 6
- Power
- FREEDOM BLDC MOTOR DRIVER SHIELD
- OrCAD Capture 16.5
sheet 2
- 1. Unless Otherwise Specified:
- All resistors are in ohms,  1% or 5%, 1/16 Watt
- All capacitors are in uF, 10%, 50V
- All voltages are DC
- All polarized capacitors are aluminum electrolytic
- 2. Interrupted lines coded with the same letter or letter
      combinations are electrically connected.
- 3. Device type number is for reference only. The number
      varies with the manufacturer.
- MCU Peripheral / Port Map
- Function
- MCU Peri
- MCU Port
- 4. Special signal usage:
- _B Denotes - Active-Low Signal
- PWM_AT
- FTM0_CH0
- PTC1
- <> or [] Denotes - Vectored Signals
- PWM_AB
- FTM0_CH1
- PTC2
- 5. Interpret diagram in accordance with American
      National Standards Institute specifications, current
      revision, with the exception of logic block symbology.
- PWM_BT
- FTM0_CH2
- PTC5
- PWM_BB
- FTM0_CH3
- PTC4
- PWM_CT
- FTM0_CH4
- PTD4
- PWM_CB
- FTM0_CH5
- PTD5
- BEMF_A
- ADC0_SE8
- PTB0
- BEMF_B
- ADC1_DP0
- ADC1_DP0
- BEMF_C
- ADC0_DP0
- ADC0_DP0
- VOLT_DCB
- ADC0_SE13
- PTB3
- CUR_DCB
- ADC1_SE18
- ADC1_SE18
- HALL_A / ENC_A
- FTM2_CH0
- PTB18
- HALL_B / ENC_B
- FTM2_CH1
- PTB19
- HALL_C / ENC_I
- FTM1_CH1
- PTA13
sheet 4
- MOSFET Gate Drivers
- Driver Power Stage
- Motor
  Output
- protect inputs when VM is not present
- Note: MOSFET Vgs = 12V max
- FS Current = 1.65V / 0.2V/A = +/-8.25A
- Gain = I * 0.01 * 20k / 1k = 0.2 V/A
- F = 1/ 2 * Pi * 20k * 10nF = 796Hz
- DCB Current Sense
- ADC Midpoint Reference
- Ref = 3.3V * 10k / 20k = 1.65V
- F = 1/ 2 * Pi * 10k||10k * 100nF = 318Hz
- Gain = Vph * 3k / (3k + 10.7k) = 0.219 * Vph
- BEMF Sense
- Gain = VM * 3k / (3k + 10.7k) = 0.219 * VM
- DCB Voltage Sense
- F = 1/ 2 * Pi * 3k||10.7k * 100nF = 679Hz
sheet 5
- Freedom / Arduino Connectors
- Output to MCU board
- Input from MCU board
- Sensor
  Input
- Hall Effect Sensor / Encoder Inputs
sheet 6
- 12V
  Motor
  Power
  Input
- 10 - 15V
- 5.5V 500mA
- Output to MCU board
- Output to encoder circuitry
- Base Board Power Supply
